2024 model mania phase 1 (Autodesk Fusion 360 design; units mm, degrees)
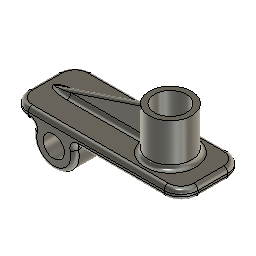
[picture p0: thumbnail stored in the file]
sketch "Sketch1" plane through (0, 0, 0) normal (0, 0, 1) x axis (1, 0, 0)
  line L1 (90, 40) -> (10, 40)
  line L2 (90, 10) -> (90, 40)
  line L3 (10, 10) -> (90, 10)
  line L4 (10, 40) -> (10, 10)
  point P2 (10, 40)
  point P3 (90, 40)
  point P5 (10, 10)
  point P1 (0, 0)
  horizontal L1
  vertical L2
  horizontal L3
  vertical L4
  dimension "d1" distance P2 P3 = 80
  dimension "d2" distance P2 P5 = 30
  dimension "d3" distance P1 L3 = 10
  dimension "d4" distance P1 L4 = 10
extrude "Extrude1" new body sketch "Sketch1" along normal blind 5
sketch "Sketch2" plane through (0, 0, 5) normal (0, 0, 1) x axis (-1, 0, 0)
  line L1 (-90, -10) -> (-10, -10)
  line L2 (-90, -40) -> (-90, -10)
  line L3 (-10, -40) -> (-90, -40)
  line L4 (-10, -10) -> (-10, -40)
  circle C1 centre (-70, -25) radius 7.5
  circle C2 centre (-70, -25) radius 10
  point P6 (-70, -25)
  concentric C1 C2
  dimension "d7" diameter C1 = 15
  dimension "d8" diameter C2 = 20
  dimension "d9" distance L3 P6 = 15
  dimension "d10" distance L2 P6 = 20
extrude "Extrude2" cut sketch "Sketch2" profile of C1 against normal blind 5
extrude "Extrude3" add sketch "Sketch2" profile of C1 C2 along normal blind 20
work_plane "WorkPlane1"
sketch "Sketch3" plane through (0, 25, 0) normal (0, 1, 0) x axis (1, 0, 0)
  line L1 (60, -5) -> (80, -5)
  line L2 (90, -5) -> (10, -5)
  line L3 (10, -5) -> (90, -5)
  line L4 (60, -20) -> (15, -5)
  line L5 (80, -25) -> (60, -25)
  line L6 (60, -5) -> (80, -5)
  line L7 (60, -5) -> (60, -25)
  line L8 (77.5, 0) -> (62.5, 0)
  line L9 (10, 0) -> (90, 0)
  line L10 (90, 0) -> (10, 0)
  line L11 (61, -20) -> (60, -20)
  line L12 (61, -5) -> (61, -20)
  circle C1 centre (30, 5) radius 5
  arc A1 centre (30, 5) radius 10 clockwise from (21.3397, 0) to (38.6603, 0)
  point P6 (15, -5)
  point P8 (60, -25)
  point P12 (60, -25)
  point P11 (60, -5)
  point P13 (60, -5)
  point P7 (60, -20)
  point P21 (38.6603, 0)
  point P22 (21.3397, 0)
  point P24 (61, -5)
  point P4 (10, -5)
  point P14 (30, 5)
  point P16 (10, 0)
  point P15 (30, 5)
  coincident L2 P6
  coincident P8 P12
  coincident P11 P13
  coincident P7 L7
  concentric C1 A1
  coincident L9 P21
  coincident L9 P22
  perpendicular L7 L11
  coincident L6 P24
  dimension "d15" distance P7 P13 = 15
  dimension "d16" distance P4 P6 = 5
  dimension "d19" diameter C1 = 10
  dimension "d20" diameter A1 = 20
  dimension "d21" distance P14 P16 = 20
  dimension "d22" distance L3 P15 = 10
extrude "Extrude4" add sketch "Sketch3" profile of L2 L3 L4 distance 1
extrude "Extrude5" add sketch "Sketch3" profile of C1 A1 L9 L10 distance 15
fillet "Fillet1" radius 8
fillet "Fillet7" radius 1
fillet "Fillet8" radius 2
fillet "Fillet9" radius 2
fillet "Fillet10" radius 2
